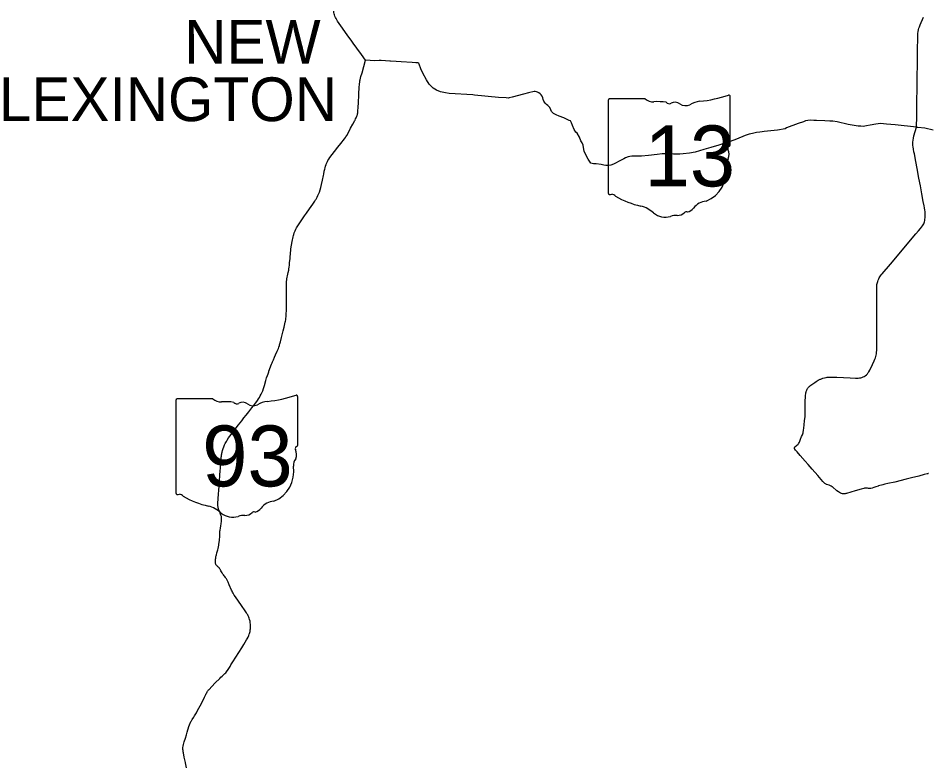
# Model space of a CAD drawing. Extents: x 1761803 to 2441803, y 509895 to 949895.
# Drawn here: x 2035458 to 2076996, y 686419 to 720477 of the extents above; entities that cross this region are included whole.
import ezdxf

# ---------------------------------------------------------------- set-up
doc = ezdxf.new("R2010")
doc.units = 0
for name, color, linetype in [('GM_X_County_Road', 7, 'Continuous'), ('GM_X_Minor_Lake', 7, 'Continuous'), ('GM_X_Township_Road', 7, 'Continuous')]:
    doc.layers.add(name, color=color, linetype=linetype)

msp = doc.modelspace()

# ---------------------------------------------------------------- linework, layer by layer
at = {"layer": 'GM_X_Minor_Lake'}
for points in [[(2050315, 719973), (2050284, 720016), (2050060, 720341), (2050023, 720395), (2049987, 720454), (2049960, 720508), (2049934, 720566), (2049913, 720624), (2049900, 720680), (2049890, 720741), (2049883, 720808), (2049883, 720948)], [(2076523, 715497), (2076526, 715533), (2076533, 715951), (2076536, 716143), (2076540, 716338), (2076544, 716771), (2076549, 717174), (2076555, 717536), (2076559, 717903), (2076563, 718272), (2076568, 718679), (2076573, 719073), (2076580, 719525), (2076581, 719644), (2076584, 719736), (2076588, 719793), (2076596, 719859), (2076615, 719953), (2076635, 720015), (2076658, 720080), (2076695, 720176), (2076839, 720520)], [(2051339, 718550), (2051145, 718818), (2050937, 719110), (2050774, 719336), (2050715, 719419), (2050499, 719717), (2050315, 719973)], [(2051074, 717586), (2051079, 717612), (2051089, 717651), (2051126, 717802), (2051177, 717976), (2051339, 718550)], [(2053665, 718433), (2053636, 718436), (2053469, 718444), (2052971, 718474), (2052744, 718493), (2052480, 718507), (2052448, 718512), (2052057, 718536), (2051959, 718542), (2051763, 718530), (2051339, 718550)], [(2056317, 716949), (2056247, 716966), (2055166, 717026), (2054991, 717055), (2054759, 717107), (2054579, 717183), (2054430, 717277), (2054349, 717347), (2054250, 717451), (2054118, 717661), (2053956, 717954), (2053866, 718163), (2053790, 718366), (2053768, 718410), (2053723, 718428), (2053665, 718433)], [(2051053, 717292), (2051067, 717472), (2051071, 717549), (2051074, 717586)], [(2050856, 715818), (2050883, 715869), (2050905, 715912), (2050928, 715954), (2050944, 715993), (2050953, 716018), (2050961, 716047), (2050967, 716068), (2050971, 716094), (2050978, 716145), (2050983, 716230), (2050995, 716412), (2051009, 716604), (2051010, 716650), (2051028, 716918), (2051038, 717073), (2051049, 717243), (2051053, 717292)], [(2058791, 717063), (2058560, 717006), (2058036, 716868), (2057910, 716827), (2057853, 716819), (2057764, 716828), (2057411, 716849), (2056317, 716949)], [(2076523, 715497), (2075554, 715599), (2075146, 715629), (2074879, 715652), (2074769, 715646), (2074667, 715632), (2074409, 715582), (2074243, 715548), (2074083, 715526), (2073980, 715531), (2073855, 715536), (2073407, 715616), (2072893, 715736), (2072705, 715761), (2072568, 715769), (2072337, 715784), (2071950, 715801), (2071836, 715802), (2071676, 715811), (2071553, 715796), (2071457, 715777), (2071363, 715742), (2071113, 715655), (2070585, 715454), (2070522, 715414), (2070163, 715351), (2069567, 715287), (2069470, 715284), (2069360, 715270), (2069203, 715241), (2069028, 715204), (2068870, 715175), (2068690, 715115), (2068297, 714937), (2068012, 714834), (2067487, 714663), (2067121, 714564), (2066800, 714475), (2066403, 714350), (2066146, 714298), (2065861, 714276), (2065704, 714260), (2065563, 714257), (2065422, 714263), (2065216, 714282), (2065135, 714279), (2064904, 714268), (2064668, 714244), (2064267, 714203), (2063950, 714166), (2063740, 714169), (2063517, 714164), (2063412, 714149), (2063348, 714133), (2063220, 714086), (2063144, 714046), (2063030, 713983), (2062673, 713796), (2062557, 713751), (2062438, 713738), (2062320, 713734), (2062228, 713749), (2062107, 713781), (2061879, 713810), (2061753, 713819), (2061631, 713844), (2061507, 714026), (2061336, 714380), (2061292, 714671), (2061234, 714780), (2061179, 714860), (2061121, 715035), (2061008, 715210), (2060950, 715265), (2060873, 715381), (2060804, 715572), (2060759, 715687), (2060702, 715782), (2060645, 715802), (2060591, 715821), (2060497, 715873), (2060398, 715914), (2060191, 715992), (2060045, 716060), (2059934, 716114), (2059892, 716154), (2059839, 716209), (2059806, 716285), (2059760, 716384), (2059739, 716415), (2059714, 716442), (2059671, 716481), (2059613, 716524), (2059564, 716568), (2059513, 716633), (2059485, 716687), (2059460, 716760), (2059438, 716837), (2059410, 716909), (2059372, 716970), (2059325, 717018), (2059263, 717069), (2059203, 717095), (2059146, 717114), (2059096, 717121), (2059045, 717120), (2058791, 717063)], [(2049543, 713803), (2049556, 713835), (2049566, 713857), (2049596, 713923), (2049618, 713961), (2049656, 714025), (2049705, 714098), (2049808, 714236), (2049916, 714376), (2050071, 714574), (2050208, 714750), (2050369, 714957), (2050420, 715023), (2050443, 715055), (2050479, 715110), (2050591, 715316), (2050656, 715440), (2050757, 715632), (2050847, 715801), (2050856, 715818)], [(2072145, 703974), (2072180, 703987), (2072246, 704010), (2072316, 704031), (2072398, 704048), (2072442, 704056), (2072478, 704060), (2072517, 704063), (2072571, 704065), (2072666, 704064), (2072886, 704057), (2073490, 704030), (2073741, 704017), (2073800, 704018), (2073857, 704018), (2073924, 704024), (2073973, 704032), (2074026, 704047), (2074080, 704068), (2074130, 704093), (2074178, 704123), (2074238, 704172), (2074281, 704215), (2074320, 704266), (2074340, 704297), (2074390, 704385), (2074516, 704640), (2074590, 704799), (2074623, 704876), (2074645, 704937), (2074666, 705004), (2074682, 705067), (2074694, 705130), (2074701, 705197), (2074707, 705276), (2074707, 706076), (2074706, 706427), (2074707, 706663), (2074705, 707129), (2074704, 707494), (2074704, 707893), (2074705, 708081), (2074707, 708179), (2074712, 708242), (2074718, 708293), (2074726, 708338), (2074738, 708391), (2074751, 708434), (2074772, 708495), (2074799, 708557), (2074819, 708595), (2074848, 708644), (2074877, 708688), (2074913, 708735), (2074949, 708783), (2075328, 709229), (2075728, 709703), (2076179, 710235), (2076494, 710607), (2076618, 710751), (2076712, 710862), (2076758, 710918), (2076805, 710980), (2076834, 711028), (2076852, 711068), (2076871, 711114), (2076887, 711165), (2076901, 711230), (2076910, 711284), (2076917, 711350), (2076923, 711449), (2076925, 711503), (2076923, 711565), (2076917, 711634), (2076909, 711694), (2076892, 711797), (2076873, 711901), (2076836, 712093), (2076771, 712442), (2076700, 712806), (2076637, 713153), (2076553, 713596), (2076490, 713927), (2076425, 714273), (2076425, 714277), (2076408, 714363), (2076385, 714478), (2076369, 714586), (2076362, 714652), (2076359, 714730), (2076359, 714808), (2076365, 714895), (2076380, 714995), (2076401, 715090), (2076523, 715497)], [(2076523, 715497), (2076588, 715490), (2076905, 715455), (2077288, 715364)], [(2049424, 713347), (2049452, 713485), (2049473, 713576), (2049487, 713629), (2049508, 713705), (2049535, 713785), (2049543, 713803)], [(2047813, 708890), (2047817, 708905), (2047826, 708955), (2047837, 709016), (2047845, 709087), (2047856, 709181), (2047868, 709307), (2047875, 709384), (2047886, 709478), (2047895, 709576), (2047905, 709684), (2047927, 709911), (2047938, 710024), (2047948, 710102), (2047979, 710269), (2048025, 710473), (2048041, 710532), (2048055, 710582), (2048078, 710659), (2048099, 710715), (2048115, 710751), (2048148, 710823), (2048182, 710885), (2048241, 710979), (2048487, 711338), (2048553, 711434), (2048645, 711565), (2048776, 711755), (2048849, 711861), (2048924, 711969), (2048985, 712060), (2049016, 712107), (2049051, 712162), (2049074, 712200), (2049122, 712288), (2049160, 712364), (2049199, 712454), (2049226, 712522), (2049263, 712631), (2049291, 712725), (2049327, 712875), (2049367, 713067), (2049409, 713274), (2049424, 713347)], [(2046910, 704302), (2046919, 704329), (2046944, 704401), (2047010, 704577), (2047040, 704650), (2047064, 704706), (2047084, 704752), (2047123, 704845), (2047178, 704973), (2047223, 705081), (2047293, 705243), (2047351, 705375), (2047372, 705427), (2047397, 705501), (2047411, 705547), (2047420, 705581), (2047447, 705681), (2047493, 705871), (2047525, 705995), (2047571, 706179), (2047613, 706349), (2047649, 706498), (2047668, 706579), (2047678, 706622), (2047689, 706680), (2047701, 706752), (2047708, 706819), (2047712, 706878), (2047715, 706942), (2047717, 707123), (2047720, 707353), (2047718, 707790), (2047718, 708072), (2047719, 708222), (2047721, 708298), (2047723, 708363), (2047726, 708416), (2047729, 708457), (2047734, 708501), (2047738, 708530), (2047743, 708562), (2047756, 708626), (2047770, 708692), (2047786, 708767), (2047802, 708838), (2047813, 708890)], [(2044632, 698893), (2044642, 699054), (2044647, 699104), (2044660, 699304), (2044679, 699578), (2044693, 699777), (2044700, 699899), (2044717, 700142), (2044730, 700298), (2044740, 700395), (2044746, 700444), (2044749, 700468), (2044755, 700511), (2044762, 700548), (2044770, 700583), (2044782, 700634), (2044799, 700700), (2044830, 700802), (2044855, 700870), (2044895, 700965), (2044926, 701030), (2044975, 701123), (2045005, 701175), (2045080, 701289), (2045128, 701356), (2045242, 701502), (2045376, 701676), (2045537, 701882), (2045682, 702068), (2045780, 702193), (2045884, 702325), (2045997, 702471), (2046145, 702656), (2046217, 702750), (2046270, 702818), (2046396, 702991), (2046447, 703068), (2046486, 703130), (2046526, 703202), (2046565, 703277), (2046609, 703373), (2046635, 703434), (2046677, 703547), (2046719, 703678), (2046781, 703902), (2046817, 704021), (2046856, 704138), (2046880, 704213), (2046910, 704302)], [(2071476, 703370), (2071485, 703402), (2071508, 703465), (2071529, 703509), (2071544, 703532), (2071559, 703555), (2071579, 703583), (2071600, 703609), (2071627, 703636), (2071652, 703659), (2071699, 703697), (2071784, 703758), (2071874, 703820), (2071936, 703860), (2071981, 703889), (2072030, 703917), (2072083, 703945), (2072127, 703967), (2072145, 703974)], [(2072331, 699199), (2072300, 699226), (2072247, 699285), (2072008, 699558), (2071755, 699852), (2071567, 700066), (2071432, 700220), (2071212, 700474), (2071066, 700640), (2071015, 700698), (2070993, 700723), (2070961, 700763), (2070949, 700787), (2070946, 700800), (2070944, 700815), (2070945, 700830), (2070947, 700842), (2070965, 700875), (2071109, 700997), (2071132, 701021), (2071149, 701041), (2071170, 701079), (2071223, 701223), (2071273, 701342), (2071309, 701423), (2071324, 701461), (2071337, 701505), (2071347, 701544), (2071359, 701623), (2071384, 701865), (2071408, 702082), (2071427, 702248), (2071436, 702342), (2071436, 702419), (2071430, 702654), (2071433, 702785), (2071436, 702881), (2071440, 702984), (2071449, 703132), (2071452, 703190), (2071456, 703242), (2071462, 703296), (2071472, 703355), (2071476, 703370)], [(2077066, 699646), (2077064, 699646), (2077036, 699642), (2077005, 699636), (2076880, 699605), (2076624, 699537), (2076289, 699453), (2076053, 699390), (2075528, 699259), (2075215, 699188), (2075071, 699158), (2074990, 699138), (2074918, 699121), (2074844, 699101), (2074794, 699085)], [(2074794, 699085), (2074766, 699076), (2074668, 699042), (2074578, 699011), (2074499, 698985), (2074438, 698971), (2074406, 698967), (2074388, 698965), (2074354, 698966), (2074325, 698969), (2074290, 698975), (2074256, 698979), (2074221, 698982), (2074190, 698983), (2074163, 698981), (2074141, 698978), (2074116, 698973), (2073994, 698940), (2073724, 698860), (2073327, 698745), (2073295, 698735), (2073270, 698728), (2073249, 698724), (2073223, 698722), (2073191, 698720), (2073165, 698721), (2073135, 698727), (2073094, 698741), (2073056, 698758), (2072960, 698812), (2072882, 698867), (2072846, 698895), (2072717, 699008), (2072681, 699037), (2072668, 699048), (2072646, 699063), (2072633, 699069), (2072617, 699078), (2072588, 699089), (2072526, 699111), (2072417, 699152), (2072387, 699166), (2072363, 699178), (2072331, 699199)], [(2044849, 695013), (2044817, 695055), (2044796, 695085), (2044781, 695107), (2044751, 695161), (2044729, 695203), (2044709, 695241), (2044695, 695265), (2044682, 695286), (2044668, 695305), (2044654, 695321), (2044628, 695350), (2044610, 695366), (2044588, 695386), (2044563, 695408), (2044538, 695433), (2044523, 695450), (2044508, 695470), (2044498, 695489), (2044488, 695511), (2044482, 695534), (2044478, 695554), (2044476, 695573), (2044476, 695599), (2044477, 695631), (2044485, 695737), (2044489, 695778), (2044494, 695817), (2044500, 695852), (2044507, 695887), (2044517, 695929), (2044542, 696017), (2044582, 696160), (2044595, 696218), (2044625, 696368), (2044653, 696535), (2044659, 696571), (2044664, 696619), (2044668, 696668), (2044670, 696720), (2044674, 696862), (2044681, 696972), (2044683, 697014), (2044688, 697060), (2044701, 697146), (2044709, 697199), (2044715, 697232), (2044743, 697388), (2044752, 697441), (2044756, 697484), (2044758, 697551), (2044757, 697610), (2044753, 697655), (2044746, 697692), (2044739, 697716), (2044727, 697753), (2044711, 697796), (2044694, 697839), (2044669, 697897), (2044649, 697944), (2044632, 697987), (2044622, 698015), (2044613, 698043), (2044603, 698084), (2044595, 698125), (2044592, 698158), (2044590, 698186), (2044589, 698225), (2044590, 698279), (2044605, 698509), (2044618, 698712), (2044631, 698884), (2044632, 698893)], [(2045186, 690896), (2045277, 691039), (2045407, 691246), (2045546, 691472), (2045676, 691682), (2045769, 691834), (2045897, 692038), (2045931, 692096), (2045969, 692172), (2046001, 692243), (2046022, 692301), (2046034, 692341), (2046045, 692379), (2046057, 692433), (2046069, 692495), (2046075, 692550), (2046078, 692594), (2046080, 692641), (2046079, 692698), (2046076, 692763), (2046069, 692823), (2046063, 692860), (2046057, 692893), (2046037, 692974), (2046016, 693040), (2046001, 693081), (2045975, 693138), (2045952, 693185), (2045931, 693225), (2045893, 693284), (2045829, 693375), (2045662, 693622), (2045527, 693815), (2045389, 694017), (2045339, 694092), (2045306, 694143), (2045280, 694186), (2045260, 694220), (2045237, 694264), (2045208, 694322), (2045104, 694553), (2045050, 694679), (2045006, 694774), (2044994, 694799), (2044977, 694829), (2044954, 694865), (2044933, 694897), (2044908, 694935), (2044893, 694954), (2044878, 694974), (2044849, 695013)], [(2043104, 686419), (2043101, 686432), (2043052, 686672), (2043010, 686884), (2043003, 686922), (2042994, 686983), (2042988, 687029), (2042986, 687068), (2042989, 687127), (2042995, 687177), (2043014, 687255), (2043049, 687378), (2043103, 687555), (2043146, 687704), (2043181, 687823), (2043258, 688082), (2043284, 688157), (2043313, 688226), (2043333, 688264), (2043356, 688310), (2043375, 688345), (2043411, 688405), (2043485, 688515), (2043518, 688565), (2043548, 688611), (2043574, 688654), (2043604, 688706), (2043647, 688780), (2043720, 688917), (2043780, 689033), (2043879, 689229), (2043976, 689425), (2044036, 689547), (2044058, 689589), (2044078, 689626), (2044098, 689661), (2044118, 689693), (2044133, 689713), (2044149, 689734), (2044165, 689755), (2044187, 689780), (2044310, 689912), (2044468, 690075), (2044673, 690284), (2044729, 690339), (2044783, 690388), (2044865, 690460), (2044909, 690499), (2044946, 690535), (2044982, 690578), (2045014, 690622), (2045030, 690646), (2045142, 690826), (2045186, 690896)], [(2043149, 686192), (2043104, 686419)]]:
    msp.add_lwpolyline(points, dxfattribs=at)
at = {"layer": 'GM_X_Township_Road'}
for p, q in [((2062433, 716713), (2062433, 712486)), ((2064118, 716786), (2062488, 716786)), ((2068001, 714679), (2068001, 716890)), ((2068001, 714680), (2068001, 714679)), ((2042666, 702991), (2042666, 698765)), ((2044352, 703064), (2042721, 703064)), ((2048235, 700958), (2048235, 703169)), ((2048234, 700958), (2048235, 700958))]:
    msp.add_line(p, q, dxfattribs=at)
for centre, radius, start, end in [((2066018, 722548), 5905, 275.8445, 288.9065), ((2067940, 716900), 62, 351.8621, 97.738), ((2062497, 716722), 64.5, 98.1301, 188.1301), ((2064507, 717276), 626, 231.6195, 271.1119), ((2064714, 714413), 2246, 80.4867, 94.9883), ((2065224, 716744), 181, 219.7921, 297.1024), ((2065489, 716255), 375, 54.4667, 119.1411), ((2065974, 716925), 452, 233.8562, 294.8282), ((2066771, 715495), 1188, 97.3462, 120.7689), ((2067987, 714517), 95.9, 107.944, 210.337), ((2067377, 714238), 576, 340.033, 23.6496), ((2067935, 714671), 66.3, 289.6038, 7.7341), ((2066349, 713473), 1477, 292.3089, 8.9858), ((2068223, 713754), 419, 136.8065, 186.9296), ((2062497, 712477), 65.1, 171.9584, 258.3066), ((2062507, 712910), 497, 267.339, 280.6039), ((2062609, 712243), 179, 29.7484, 93.2717), ((2064870, 716040), 4265, 240.4129, 257.1985), ((2066971, 711300), 809, 94.4031, 142.5768), ((2063598, 710588), 1334, 47.1842, 75.836), ((2065041, 712222), 847, 230.7004, 286.2918), ((2065592, 711905), 451, 268.777, 315.5493), ((2066001, 711496), 127, 65.7517, 132.6484), ((2065946, 712077), 477, 282.8732, 323.2771), ((2065531, 710760), 696, 85.6951, 111.2099), ((2042730, 703000), 64.5, 98.1301, 188.1301), ((2044740, 703555), 626, 231.6195, 271.1119), ((2044948, 700691), 2246, 80.4867, 94.9883), ((2045458, 703022), 181, 219.7921, 297.1024), ((2045723, 702534), 375, 54.4667, 119.1411), ((2046207, 703204), 452, 233.8562, 294.8282), ((2047004, 701773), 1188, 97.3462, 120.7689), ((2046251, 708826), 5905, 275.8445, 288.9065), ((2048173, 703178), 62, 351.8621, 97.738), ((2048221, 700796), 95.9, 107.944, 210.337), ((2048169, 700949), 66.3, 289.6038, 7.7341), ((2047610, 700516), 576, 340.033, 23.6496), ((2046582, 699751), 1477, 292.3089, 8.9858), ((2048457, 700033), 419, 136.8065, 186.9296), ((2042731, 698756), 65.1, 171.9584, 258.3066), ((2042740, 699188), 497, 267.339, 280.6039), ((2042842, 698521), 179, 29.7484, 93.2717), ((2045103, 702318), 4265, 240.4129, 257.1985), ((2047205, 697578), 809, 94.4031, 142.5768), ((2043832, 696866), 1334, 47.1842, 75.836), ((2045275, 698500), 847, 230.7004, 286.2918), ((2045826, 698184), 451, 268.777, 315.5493), ((2046234, 697774), 127, 65.7517, 132.6484), ((2046180, 698355), 477, 282.8732, 323.2771), ((2045764, 697039), 696, 85.6951, 111.2099)]:
    msp.add_arc(centre, radius, start, end, dxfattribs=at)

# ---------------------------------------------------------------- texts
at = {"layer": 'GM_X_County_Road'}
for s, p in [('NEW', (2043047, 718399)), ('LEXINGTON', (2034576, 715767))]:
    msp.add_text(s, height=2000, rotation=0, dxfattribs=at).set_placement(p)
at = {"layer": 'GM_X_Township_Road'}
for s, p in [('13', (2064091, 712784)), ('93', (2043868, 699063))]:
    msp.add_text(s, height=2784.4, dxfattribs=at).set_placement(p)

doc.saveas('drawing.dxf')
